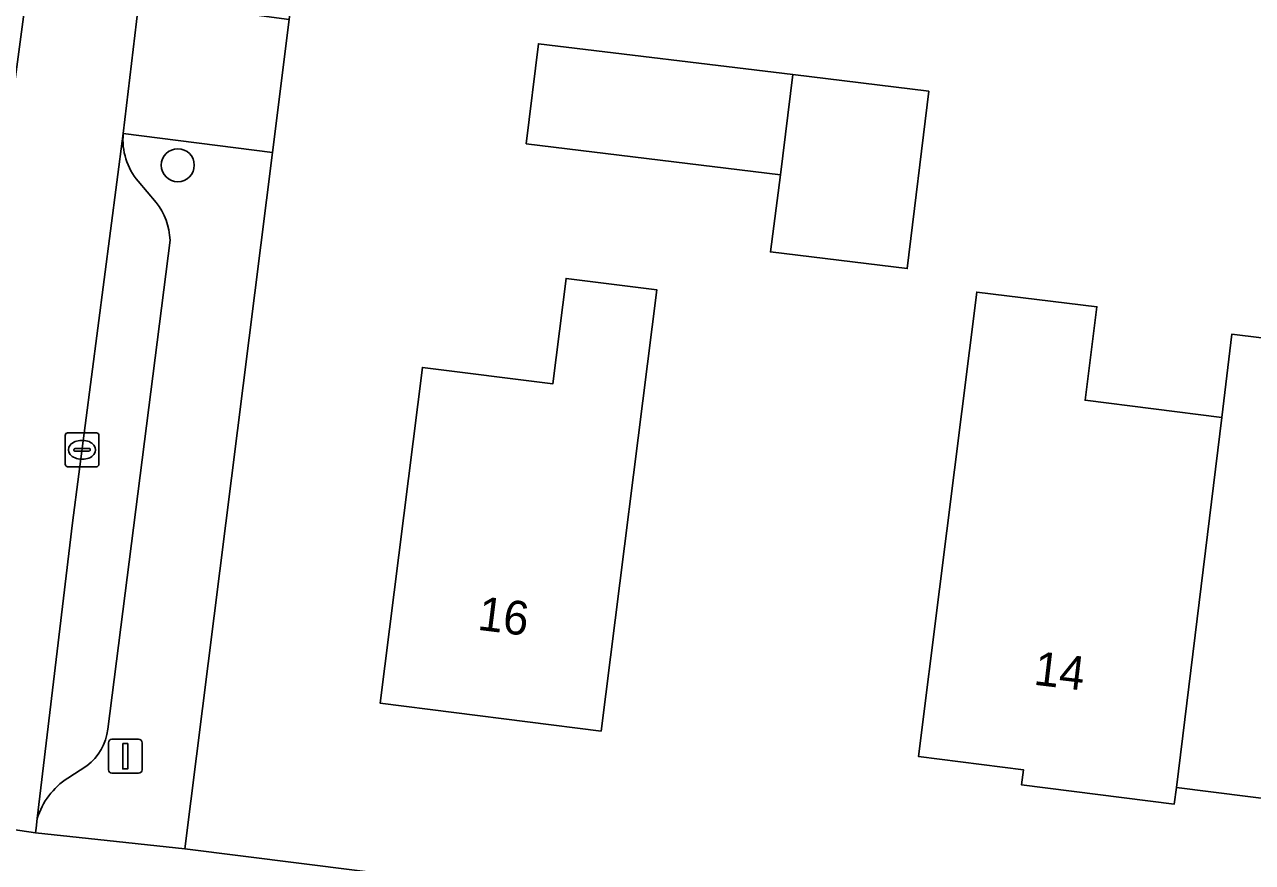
# Model space of a CAD drawing. Extents: x 161258 to 161838, y 380833 to 381727.
# Drawn here: x 161626.44 to 161662.78, y 381360.15 to 381384.97 of the extents above; entities that cross this region are included whole.
import ezdxf

# ---------------------------------------------------------------- set-up
doc = ezdxf.new("R2010")
doc.units = 0
for name, color, linetype in [('IMGEO_Boom', 7, 'Continuous'), ('IMGEO_Erf', 7, 'Continuous'), ('IMGEO_Kolk', 7, 'Continuous'), ('IMGEO_Lichtmast', 7, 'Continuous'), ('IMGEO_Pand', 7, 'Continuous'), ('IMGEO_Pand_nummerreeks', 7, 'Continuous'), ('IMGEO_Parkeervlak_open', 7, 'Continuous'), ('IMGEO_Rijbaan_lokaal_open', 7, 'Continuous'), ('IMGEO_Voetpad_open', 7, 'Continuous')]:
    doc.layers.add(name, color=color, linetype=linetype)

msp = doc.modelspace()

# ---------------------------------------------------------------- linework, layer by layer
at = {"layer": 'IMGEO_Boom'}
msp.add_circle((161630.973, 381380.803), 0.489, dxfattribs=at)
at = {"layer": 'IMGEO_Erf'}
msp.add_lwpolyline([(161632.557, 381433.385), (161638.239, 381417.444), (161637.547, 381412.742), (161634.273, 381385.117), (161633.778, 381381.183), (161631.183, 381360.562), (161646.49, 381358.638), (161649.876, 381358.212), (161669.686, 381355.721)], dxfattribs=at)
for points in [[(161653.203, 381382.992), (161652.564, 381377.744), (161648.516, 381378.237), (161648.815, 381380.521), (161641.286, 381381.438), (161641.648, 381384.402), (161649.176, 381383.485)], [(161643.508, 381364.046), (161636.964, 381364.868), (161638.215, 381374.816), (161642.075, 381374.33), (161642.468, 381377.453), (161645.151, 381377.115)], [(161664.964, 381375.453), (161664.351, 381370.574), (161669.196, 381369.965), (161668.698, 381366.006), (161670.713, 381365.753), (161670.136, 381361.169), (161667.027, 381361.559), (161660.531, 381362.376), (161660.47, 381361.885), (161655.947, 381362.454), (161656.003, 381362.9), (161652.899, 381363.29), (161653.522, 381368.251), (161654.621, 381377.046), (161658.181, 381376.613), (161657.832, 381373.841), (161661.873, 381373.334), (161662.175, 381375.804)]]:
    msp.add_lwpolyline(points, close=True, dxfattribs=at)
at = {"layer": 'IMGEO_Kolk'}
for p, q in [((161627.638, 381371.949), (161627.638, 381372.801)), ((161627.713, 381372.875), (161628.565, 381372.875)), ((161628.639, 381372.801), (161628.639, 381371.949)), ((161627.897, 381372.369), (161627.897, 381372.381)), ((161627.94, 381372.418), (161628.338, 381372.418)), ((161628.126, 381372.655), (161628.151, 381372.655)), ((161628.381, 381372.381), (161628.381, 381372.369)), ((161628.335, 381372.332), (161627.937, 381372.332)), ((161628.149, 381372.095), (161628.124, 381372.095)), ((161628.565, 381371.875), (161627.713, 381371.875))]:
    msp.add_line(p, q, dxfattribs=at)
for points in [[(161627.638, 381371.949), (161627.638, 381372.801)], [(161627.713, 381372.875), (161628.565, 381372.875)], [(161628.639, 381372.801), (161628.639, 381371.949)], [(161628.565, 381371.875), (161627.713, 381371.875)]]:
    msp.add_lwpolyline(points, dxfattribs=at)
for centre, radius, start, end in [((161627.715, 381372.799), 0.0765, 91.552, 178.448), ((161627.715, 381372.799), 0.0765, 91.552, 178.448), ((161628.563, 381372.799), 0.0765, 1.552, 88.448), ((161628.563, 381372.799), 0.0765, 1.552, 88.448), ((161627.937, 381372.378), 0.0403, 85.8775, 175.7526), ((161627.934, 381372.368), 0.0366, 178.938, 274.7102), ((161628.338, 381372.375), 0.043, 264.8664, 352.4533), ((161628.342, 381372.38), 0.0386, 1.7309, 96.639), ((161627.715, 381371.951), 0.0765, 181.552, 268.448), ((161627.715, 381371.951), 0.0765, 181.552, 268.448), ((161628.563, 381371.951), 0.0765, 271.552, 358.448), ((161628.563, 381371.951), 0.0765, 271.552, 358.448)]:
    msp.add_arc(centre, radius, start, end, dxfattribs=at)
for centre, major_axis, ratio, start_param, end_param in [((161628.125, 381372.375), (-0.387, 0.002), 0.722429, 4.712389, 7.853982), ((161628.15, 381372.375), (-0.39, 0.002), 0.717154, 1.570796, 4.712389)]:
    msp.add_ellipse(centre, major_axis=major_axis, ratio=ratio, start_param=start_param, end_param=end_param, dxfattribs=at)
at = {"layer": 'IMGEO_Lichtmast'}
for p, q in [((161628.924, 381362.901), (161628.924, 381363.701)), ((161628.924, 381363.701), (161628.924, 381362.901)), ((161629.024, 381363.801), (161629.814, 381363.801)), ((161629.814, 381363.801), (161629.024, 381363.801)), ((161629.914, 381363.701), (161629.914, 381362.901)), ((161629.914, 381362.901), (161629.914, 381363.701)), ((161629.814, 381362.801), (161629.024, 381362.801)), ((161629.024, 381362.801), (161629.814, 381362.801))]:
    msp.add_line(p, q, dxfattribs=at)
msp.add_lwpolyline([(161629.344, 381363.676), (161629.494, 381363.676), (161629.494, 381362.926), (161629.344, 381362.926), (161629.344, 381363.676)], dxfattribs=at)
for centre, start, end in [((161629.024, 381363.701), 90, 180), ((161629.024, 381363.701), 90, 180), ((161629.814, 381363.701), 0, 90), ((161629.814, 381363.701), 360, 90), ((161629.024, 381362.901), 180, 270), ((161629.024, 381362.901), 180, 270), ((161629.814, 381362.901), 270, 0), ((161629.814, 381362.901), 270, 0)]:
    msp.add_arc(centre, 0.1, start, end, dxfattribs=at)
at = {"layer": 'IMGEO_Pand'}
for points in [[(161648.815, 381380.521), (161649.176, 381383.485), (161641.648, 381384.402), (161641.286, 381381.438)], [(161649.176, 381383.485), (161648.815, 381380.521), (161648.516, 381378.237), (161652.564, 381377.744), (161653.203, 381382.992)], [(161643.508, 381364.046), (161645.151, 381377.115), (161642.468, 381377.453), (161642.075, 381374.33), (161638.215, 381374.816), (161636.964, 381364.868)], [(161661.873, 381373.334), (161657.832, 381373.841), (161658.181, 381376.613), (161654.621, 381377.046), (161653.522, 381368.251), (161652.899, 381363.29), (161656.003, 381362.9), (161655.947, 381362.454), (161660.47, 381361.885), (161660.531, 381362.376)], [(161669.196, 381369.965), (161664.351, 381370.574), (161664.964, 381375.453), (161662.175, 381375.804), (161661.873, 381373.334), (161660.531, 381362.376), (161667.027, 381361.559), (161670.136, 381361.169), (161670.713, 381365.753), (161668.698, 381366.006)]]:
    msp.add_lwpolyline(points, close=True, dxfattribs=at)
at = {"layer": 'IMGEO_Parkeervlak_open'}
for points in [[(161629.358, 381381.739), (161627.856, 381370.215), (161626.812, 381361.453)], [(161630.329, 381379.702), (161629.798, 381380.326)], [(161628.898, 381364.105), (161630.743, 381378.584)], [(161627.716, 381362.653), (161628.285, 381363.016)]]:
    msp.add_lwpolyline(points, dxfattribs=at)
for centre, radius, start, end in [((161631.279, 381381.562), 1.929, 174.7412, 219.8514), ((161628.825, 381378.51), 1.919, 2.2244, 38.4152), ((161627.292, 381364.292), 1.617, 307.8954, 353.3541), ((161628.936, 381360.793), 2.225, 123.2717, 162.7445)]:
    msp.add_arc(centre, radius, start, end, dxfattribs=at)
at = {"layer": 'IMGEO_Rijbaan_lokaal_open'}
msp.add_lwpolyline([(161630.074, 381414.521), (161629.886, 381413.343), (161629.229, 381408.041), (161627.951, 381398.186), (161627.937, 381398.058), (161626.958, 381389.351), (161626.112, 381382.98), (161626.09, 381382.805), (161624.952, 381373.802), (161623.53, 381361.715), (161623.507, 381361.52), (161626.762, 381361.028), (161626.779, 381361.172), (161626.812, 381361.453), (161627.856, 381370.215), (161629.358, 381381.739), (161629.854, 381385.901), (161630.024, 381387.329), (161631.028, 381395.148)], dxfattribs=at)
msp.add_lwpolyline([(161631.183, 381360.562), (161628.33, 381360.863), (161626.762, 381361.028), (161623.507, 381361.52), (161619.194, 381362.168), (161601.597, 381364.408), (161602.107, 381361.121), (161619.999, 381358.857), (161629.727, 381357.627), (161633.186, 381357.189), (161635.335, 381356.92), (161640.396, 381356.267), (161646.108, 381355.537), (161646.49, 381358.638)], close=True, dxfattribs=at)
at = {"layer": 'IMGEO_Voetpad_open'}
msp.add_lwpolyline([(161634.273, 381385.117), (161631.303, 381385.513), (161631.355, 381385.691), (161629.854, 381385.901), (161629.358, 381381.739), (161633.778, 381381.183)], close=True, dxfattribs=at)
for points in [[(161633.778, 381381.183), (161629.358, 381381.739)], [(161626.812, 381361.453), (161626.779, 381361.172), (161626.762, 381361.028), (161628.33, 381360.863), (161631.183, 381360.562), (161633.778, 381381.183)], [(161629.798, 381380.326), (161630.329, 381379.702)], [(161630.743, 381378.584), (161628.898, 381364.105)], [(161628.285, 381363.016), (161627.716, 381362.653)]]:
    msp.add_lwpolyline(points, dxfattribs=at)
for centre, radius, start, end in [((161631.279, 381381.562), 1.929, 174.7412, 219.8514), ((161628.825, 381378.51), 1.919, 2.2244, 38.4152), ((161627.292, 381364.292), 1.617, 307.8954, 353.3541), ((161628.936, 381360.793), 2.225, 123.2717, 162.7445)]:
    msp.add_arc(centre, radius, start, end, dxfattribs=at)

# ---------------------------------------------------------------- texts
at = {"layer": 'IMGEO_Pand_nummerreeks'}
for s, rotation, p in [('16', 352.8405, (161639.82, 381367.049)), ('14', 353.1703, (161656.284, 381365.422))]:
    msp.add_text(s, height=1, rotation=rotation, dxfattribs=at).set_placement(p)

doc.saveas('drawing.dxf')
